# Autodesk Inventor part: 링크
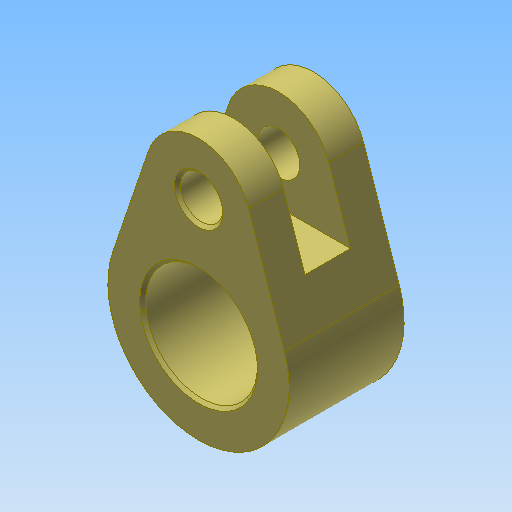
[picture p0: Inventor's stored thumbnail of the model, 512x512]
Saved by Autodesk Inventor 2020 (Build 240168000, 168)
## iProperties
Created: 2010-03
Part Number: 링크
Document SubType Name: Modeling
Designer: Administrator
Density: 1 g/cm^3
Material: 스테인리스강
Appearance: 기본값(1)
Author: Administrator
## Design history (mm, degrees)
sketch "스케치1"
  geometry: L1 (-16.577, 44.609)-(-28.417, 9.615); L2 (16.577, 44.609)-(28.417, 9.615); C1 r 18.5 at (0, 0); C2 r 7 at (0, 39); A1 r 30 centre (0, 0) between (28.417, 9.615) and (-28.417, 9.615); A2 r 17.5 centre (0, 39) between (-16.577, 44.609) and (16.577, 44.609); 1 further point
  constraints: 4 centre point, 4 end point, 4 point on circle, 4 tangent, 3 coincident, 1 vertical alignment
  dimensions: "d0" = 37 diameter of C1; "d1" = 60 diameter of A1; "d2" = 35 diameter of A2; "d3" = 39 distance of A1.centre A2.centre; "d4" = 14 diameter of C2
extrude "돌출1" new body sketch "스케치1" distance "d5" = 38; taper "d6" = 0 deg
sketch "스케치2"
  geometry: L1 (32, 38)-(32, 0) reference; L2 (32, 0)-(18.5, 0) reference; L3 (18.5, 0)-(18.5, 38) reference; L4 (18.5, 38)-(32, 38) reference; L5 (-30, 0)-(-30, 38) reference; L6 (-30, 38)-(-18.5, 38) reference; L7 (-18.5, 38)-(-18.5, 0) reference; L8 (-18.5, 0)-(-30, 0) reference; L9 (56.5, 38)-(56.5, 0) reference; L10 (56.5, 0)-(46, 0) reference; L11 (46, 0)-(46, 38) reference; L12 (46, 38)-(56.5, 38) reference; L13 (79.593, 11.5)-(23.5, 11.5); L14 (23.5, 11.5)-(23.5, 26.5); L15 (23.5, 26.5)-(79.593, 26.5); L16 (79.593, 26.5)-(79.593, 11.5); 3 further points
  constraints: 8 end point, 2 midpoint, 2 parallel, 1 horizontal, 1 horizontal alignment, 1 perpendicular
  dimensions: "d7" = 33 distance between parallel lines of L14 L9; "d8" = 15 distance of L15.end L13.start
extrude "돌출2" cut sketch "스케치2" extent not by distance; stored distance "d9" = 26; taper "d10" = 0 deg
chamfer "모따기1" distance "d11" = 1; stored, may be unused: second distance "d12" = 2, angle "d13" = 45 deg
node "솔리드1"
node "절단 모서리 투영1"
